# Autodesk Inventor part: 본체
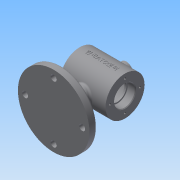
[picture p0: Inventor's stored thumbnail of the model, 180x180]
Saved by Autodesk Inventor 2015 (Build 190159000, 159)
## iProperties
Created: 2018-12
Part Number: 본체
Material: 일반
Document SubType Name: Modeling
Designer: 405-15
Density: 1 g/cm^3
Appearance: 기본값
Author: 405-15
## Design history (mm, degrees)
sketch "스케치1"
  geometry: C1 r 55 at (0, 0); 1 further point
  constraints: 1 centre point, 1 coincident
  dimensions: "d0" = 110 diameter of C1
extrude "돌출1" new body sketch "스케치1" distance "d1" = 11; taper "d2" = 0 deg
sketch "스케치2"
  geometry: L1 (0, 11)-(0, 25.737); L2 (0, 25.737)-(55, 11); L3 (55, 11)-(-55, 11) reference; L4 (0, 11)-(55, 11); 1 further point
  constraints: 7 end point, 1 collinear, 1 midpoint, 1 point on line, 1 vertical
  dimensions: "d4" = 15 deg angle of L3 L2
revolve "회전1" sketch "스케치2" stored, may be unused: angle "d5" = 90 deg
sketch "스케치3"
  geometry: L1 (0, 0)-(75, 0); C1 r 30 at (75, 0)
  constraints: 2 end point, 1 centre point, 1 coincident, 1 horizontal
  dimensions: "d6" = 75 distance of L1.start L1.end; "d7" = 60 diameter of C1
extrude "돌출2" join sketch "스케치3" stored distance "d8" = 70; taper "d9" = 0 deg
sketch "스케치4"
  geometry: C1 r 12 at (0, 0); 1 further point
  constraints: 1 centre point, 1 coincident
  dimensions: "d10" = 24 diameter of C1
extrude "돌출3" join sketch "스케치4" stored distance "d11" = 70; taper "d12" = 0 deg
sketch "스케치5"
  geometry: C1 r 30 at (0, 0) reference; C2 r 16 at (0, 0); 1 further point
  constraints: 1 centre point, 1 coincident
  dimensions: "d14" = 32 diameter of C2
extrude "돌출4" cut sketch "스케치5" distance "d15" = 12; taper "d16" = 0 deg
sketch "스케치6"
  geometry: C1 r 16 at (0, 0) reference; C2 r 14 at (0, 0); 1 further point
  constraints: 1 centre point, 1 coincident
  dimensions: "d17" = 28 diameter of C2
extrude "돌출5" cut sketch "스케치6" distance "d18" = 3; taper "d19" = 0 deg
sketch "스케치7"
  geometry: C1 r 14 at (0, 0) reference; C2 r 25 at (0, 0); 1 further point
  constraints: 1 centre point, 1 coincident
  dimensions: "d20" = 50 diameter of C2
extrude "돌출6" cut sketch "스케치7" distance "d21" = 40; taper "d22" = 0 deg
node "작업 평면1"
sketch "스케치8"
  geometry: C1 r 10 at (0, 0); 1 further point
  constraints: 1 centre point, 1 coincident
  dimensions: "d24" = 20 diameter of C1
extrude "돌출7" join sketch "스케치8" stored distance "d25" = 40; taper "d26" = 0 deg
sketch "스케치9"
  geometry: C1 r 5 at (0, 0); 1 further point
  constraints: 1 centre point, 1 coincident
  dimensions: "d27" = 10 diameter of C1
extrude "돌출8" cut sketch "스케치9" stored distance "d28" = 40; taper "d29" = 0 deg
sketch "스케치10" dims "d31" = 46
  geometry: C1 r 30 at (0, 0) reference; 3 further points
  constraints: 1 coincident, 1 vertical alignment, 2 other
hole "구멍1" sketch "스케치10" at (0, 23) diameter "d32" = 3.242; stored, may be unused: countersink angle "d36" = 90 deg, drill point angle "d38" = 118 deg; dims "d33" = 8, "d34" = 4, "d35" = 2, "d37" = 10
fillet "모깎기1" dims "d42" = 0.3
fillet "모깎기2" dims "d43" = 3
fillet "모깎기3" dims "d44" = 3
chamfer "모따기1" distance "d45" = 1; stored, may be unused: second distance "d46" = 2, angle "d47" = 45 deg
sketch "스케치11" dims "d48" = 88
  geometry: C1 r 6 at (0, 0) reference; C2 r 4.5 at (0, 44); 2 further points
  constraints: 2 vertical alignment, 1 centre point, 1 coincident, 2 other
  dimensions: "d74" = 9 diameter of C2
node "작업 평면2"
sketch "스케치12" dims "d1" = 11, "d2" = 0
  geometry: L1 (-35, 105)-(-35, 45) reference; L2 (-35, 105)-(35, 105) reference; L3 (-24.887, 78.602)-(24.887, 78.602); L4 (24.887, 78.602)-(24.887, 71.398); L5 (24.887, 71.398)-(-24.887, 71.398); L6 (-24.887, 71.398)-(-24.887, 78.602); L7 (0, 78.602)-(0, 71.398); L8 (0, 75)-(-24.887, 75); 1 further point
  constraints: 4 end point, 4 midpoint, 2 other
  dimensions: "d70" = 35 distance from line of L8.start L1; "d71" = 30 distance from line of L8.start L2
feature "엠보싱1" sketch "스케치12" dims "d1" = 11, "d2" = 0, "d72" = 0.5, "d73" = 0
extrude "돌출9" cut sketch "스케치11" distance "d75" = 10; taper "d76" = 0 deg
sketch "스케치13"
  geometry: C1 r 4.5 at (0, 0) reference; C2 r 7 at (0, 0); 1 further point
  constraints: 1 centre point, 1 coincident
  dimensions: "d77" = 14 diameter of C2
extrude "돌출10" cut sketch "스케치13" stored distance "d78" = 10; taper "d79" = 0 deg
node "솔리드1"
mirror "대칭1"
pattern_circular "원형 패턴1" dims angle "d40" = 360 deg
mirror "대칭2"
pattern_circular "원형 패턴3" dims angle "d81" = 360 deg
other parameters: "d23" = -112
